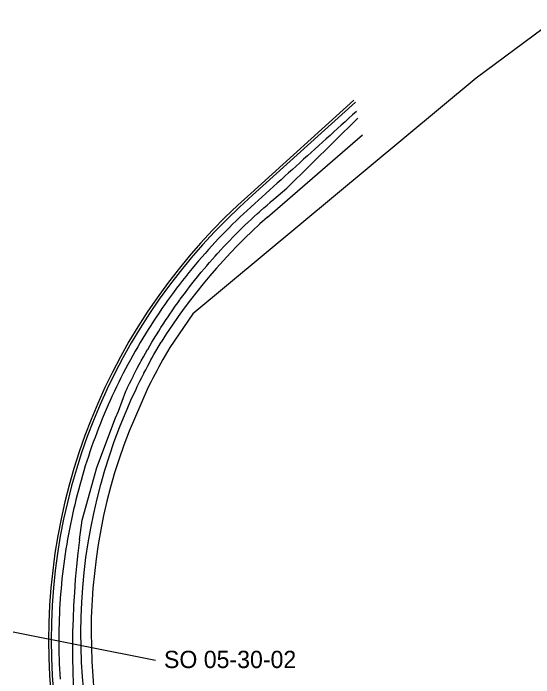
# Model space of a CAD drawing. Extents: x -723225 to -722352, y -1040354 to -1039760.
# Drawn here: x -722611.1 to -722559.9, y -1040117.7 to -1040052.4 of the extents above; entities that cross this region are included whole.
import ezdxf

# ---------------------------------------------------------------- set-up
doc = ezdxf.new("R2010")
doc.units = 0
for name, color, linetype in [('_PS_SO_číslo', 7, 'Continuous'), ('SO 05_30_02', 7, 'Continuous'), ('SO 05_73_06', 7, 'Continuous')]:
    doc.layers.add(name, color=color, linetype=linetype)

msp = doc.modelspace()

# ---------------------------------------------------------------- linework, layer by layer
at = {"layer": '_PS_SO_číslo'}
msp.add_line((-722611.08, -1040113.25), (-722597.09, -1040116.03), dxfattribs=at)
at = {"layer": 'SO 05_30_02'}
for p, q in [((-722577.569, -1040060.933), (-722587.7, -1040070.108)), ((-722577.401, -1040061.118), (-722587.532, -1040070.293)), ((-722586.071, -1040072.432), (-722576.706, -1040064.349))]:
    msp.add_line(p, q, dxfattribs=at)
for points in [[(-722577.314, -1040062.051), (-722577.684, -1040062.387), (-722578.054, -1040062.722), (-722578.054, -1040062.722), (-722578.425, -1040063.058), (-722578.425, -1040063.058), (-722578.795, -1040063.393), (-722579.166, -1040063.729), (-722579.537, -1040064.064), (-722579.907, -1040064.4), (-722580.278, -1040064.736), (-722580.648, -1040065.071), (-722580.649, -1040065.071), (-722581.019, -1040065.407), (-722581.019, -1040065.407), (-722581.39, -1040065.742), (-722581.761, -1040066.078), (-722582.131, -1040066.414), (-722582.502, -1040066.749), (-722582.872, -1040067.084), (-722583.243, -1040067.421), (-722583.613, -1040067.756), (-722583.614, -1040067.756), (-722583.984, -1040068.092), (-722583.984, -1040068.092), (-722584.354, -1040068.427), (-722584.725, -1040068.763), (-722584.725, -1040068.763), (-722585.096, -1040069.099), (-722585.096, -1040069.099), (-722585.467, -1040069.435), (-722585.838, -1040069.77), (-722585.838, -1040069.77), (-722586.209, -1040070.105), (-722586.209, -1040070.106), (-722586.58, -1040070.441), (-722586.951, -1040070.776), (-722586.951, -1040070.776), (-722587.323, -1040071.111), (-722587.323, -1040071.112), (-722587.695, -1040071.446), (-722588.061, -1040071.78), (-722588.422, -1040072.115), (-722588.784, -1040072.455), (-722589.134, -1040072.794), (-722589.495, -1040073.142), (-722589.837, -1040073.487), (-722590.189, -1040073.841), (-722590.528, -1040074.193), (-722590.873, -1040074.552), (-722591.211, -1040074.911), (-722591.544, -1040075.273), (-722591.876, -1040075.639), (-722592.202, -1040076.007), (-722592.532, -1040076.381), (-722592.848, -1040076.751), (-722593.173, -1040077.132), (-722593.486, -1040077.509), (-722593.799, -1040077.891), (-722594.106, -1040078.275), (-722594.414, -1040078.664), (-722594.715, -1040079.054), (-722595.012, -1040079.445), (-722595.31, -1040079.843), (-722595.6, -1040080.24), (-722595.889, -1040080.64), (-722596.176, -1040081.044), (-722596.451, -1040081.445), (-722596.734, -1040081.858), (-722597.012, -1040082.269), (-722597.283, -1040082.679), (-722597.549, -1040083.093), (-722597.812, -1040083.509), (-722598.078, -1040083.932), (-722598.323, -1040084.345), (-722598.578, -1040084.774), (-722598.834, -1040085.205), (-722599.081, -1040085.631), (-722599.316, -1040086.055), (-722599.557, -1040086.492), (-722599.558, -1040086.492), (-722599.8, -1040086.93), (-722600.027, -1040087.359), (-722600.256, -1040087.799), (-722600.479, -1040088.237), (-722600.697, -1040088.678), (-722600.915, -1040089.124), (-722601.127, -1040089.569), (-722601.334, -1040090.015), (-722601.54, -1040090.466), (-722601.74, -1040090.916), (-722601.938, -1040091.369), (-722602.13, -1040091.823), (-722602.319, -1040092.279), (-722602.505, -1040092.737), (-722602.685, -1040093.195), (-722602.862, -1040093.656), (-722603.033, -1040094.117), (-722603.205, -1040094.584), (-722603.366, -1040095.045), (-722603.531, -1040095.517), (-722603.688, -1040095.982), (-722603.842, -1040096.452), (-722603.991, -1040096.922), (-722604.136, -1040097.393), (-722604.277, -1040097.866), (-722604.412, -1040098.338), (-722604.545, -1040098.816), (-722604.677, -1040099.295), (-722604.801, -1040099.77), (-722604.92, -1040100.246), (-722605.038, -1040100.729), (-722605.147, -1040101.206), (-722605.259, -1040101.692), (-722605.363, -1040102.173), (-722605.462, -1040102.655), (-722605.556, -1040103.138), (-722605.649, -1040103.625), (-722605.736, -1040104.111), (-722605.818, -1040104.596), (-722605.895, -1040105.082), (-722605.895, -1040105.082), (-722605.974, -1040105.576), (-722606.044, -1040106.061), (-722606.112, -1040106.551), (-722606.173, -1040107.037), (-722606.233, -1040107.531), (-722606.287, -1040108.021), (-722606.334, -1040108.508), (-722606.383, -1040109.005), (-722606.422, -1040109.491), (-722606.46, -1040109.987), (-722606.49, -1040110.476), (-722606.522, -1040110.975), (-722606.543, -1040111.46), (-722606.564, -1040111.958), (-722606.58, -1040112.452), (-722606.587, -1040112.938), (-722606.595, -1040113.438), (-722606.601, -1040113.937), (-722606.599, -1040114.424), (-722606.591, -1040114.926), (-722606.583, -1040115.414), (-722606.574, -1040115.914), (-722606.551, -1040116.39), (-722606.528, -1040116.89), (-722606.503, -1040117.388), (-722606.476, -1040117.882)], [(-722601.012, -1040092.171), (-722600.737, -1040091.518), (-722600.378, -1040090.55), (-722600.005, -1040089.57), (-722599.884, -1040089.313), (-722599.825, -1040089.19), (-722599.641, -1040088.811), (-722599.454, -1040088.433), (-722599.265, -1040088.057), (-722599.24, -1040088.008), (-722599.072, -1040087.682), (-722598.877, -1040087.309), (-722598.679, -1040086.938), (-722598.562, -1040086.72), (-722598.478, -1040086.567), (-722598.274, -1040086.199), (-722598.068, -1040085.832), (-722597.859, -1040085.466), (-722597.85, -1040085.451), (-722597.647, -1040085.102), (-722597.432, -1040084.74), (-722597.214, -1040084.379), (-722597.105, -1040084.201), (-722596.994, -1040084.02), (-722596.771, -1040083.663), (-722596.578, -1040083.358), (-722596.545, -1040083.307), (-722596.328, -1040082.971), (-722596.317, -1040082.954), (-722596.086, -1040082.601), (-722595.852, -1040082.251), (-722595.616, -1040081.903), (-722595.519, -1040081.761), (-722595.377, -1040081.556), (-722595.135, -1040081.211), (-722594.891, -1040080.868), (-722594.678, -1040080.574), (-722594.644, -1040080.527), (-722594.394, -1040080.187), (-722594.142, -1040079.85), (-722593.888, -1040079.514), (-722593.807, -1040079.409), (-722593.631, -1040079.181), (-722593.371, -1040078.849), (-722593.109, -1040078.52), (-722592.905, -1040078.267), (-722592.844, -1040078.192), (-722592.577, -1040077.866), (-722592.307, -1040077.543), (-722592.035, -1040077.221), (-722591.973, -1040077.149), (-722591.76, -1040076.902), (-722591.484, -1040076.585), (-722591.204, -1040076.27), (-722591.012, -1040076.056), (-722590.985, -1040076.025), (-722590.922, -1040075.956), (-722590.638, -1040075.646), (-722590.352, -1040075.337), (-722590.063, -1040075.03), (-722590.023, -1040074.988), (-722589.772, -1040074.726), (-722589.478, -1040074.424), (-722589.183, -1040074.124), (-722589.007, -1040073.947), (-722588.885, -1040073.826), (-722588.584, -1040073.531), (-722588.282, -1040073.238), (-722587.977, -1040072.947), (-722587.963, -1040072.934), (-722587.67, -1040072.659), (-722587.361, -1040072.373), (-722587.05, -1040072.089), (-722586.893, -1040071.947), (-722586.737, -1040071.808), (-722586.421, -1040071.529), (-722586.103, -1040071.252), (-722585.797, -1040070.99), (-722585.783, -1040070.977), (-722585.435, -1040070.681), (-722584.149, -1040069.586), (-722577.187, -1040062.719), (-722577.187, -1040062.719)], [(-722604.18, -1040118.698), (-722604.268, -1040117.676), (-722604.36, -1040116.208), (-722604.414, -1040114.738), (-722604.43, -1040113.268), (-722604.406, -1040111.797), (-722604.344, -1040110.327), (-722604.284, -1040109.376), (-722604.244, -1040108.86), (-722604.105, -1040107.395), (-722603.928, -1040105.935), (-722603.712, -1040104.48), (-722603.458, -1040103.031), (-722603.166, -1040101.59), (-722602.839, -1040100.166), (-722602.837, -1040100.156), (-722602.47, -1040098.732), (-722602.065, -1040097.318), (-722601.624, -1040095.915), (-722601.146, -1040094.523), (-722600.632, -1040093.145), (-722600.081, -1040091.781), (-722599.887, -1040091.324), (-722599.495, -1040090.432), (-722598.998, -1040089.358), (-722598.874, -1040089.099), (-722598.814, -1040088.975), (-722598.626, -1040088.592), (-722598.436, -1040088.212), (-722598.243, -1040087.832), (-722598.218, -1040087.783), (-722598.047, -1040087.454), (-722597.848, -1040087.078), (-722597.647, -1040086.703), (-722597.527, -1040086.484), (-722597.442, -1040086.329), (-722597.235, -1040085.958), (-722596.541, -1040084.735)], [(-722604.567, -1040104.198), (-722604.295, -1040102.259), (-722603.517, -1040099.442), (-722602.86, -1040097.061), (-722601.012, -1040092.171)]]:
    msp.add_lwpolyline(points, dxfattribs=at)
for radius in [58.46, 58.21]:
    msp.add_arc((-722549.145, -1040114.051), radius, 131.25938, 185.13439, dxfattribs=at)
for centre, major_axis, ratio, start_param, end_param in [((-722548.371, -1040115.029), (-39.084, -42.585), 0.983948, 4.610283, 4.890699), ((-722517.018, -1040111.528), (79.312, 40.575), 0.952893, 2.563333, 2.804578)]:
    msp.add_ellipse(centre, major_axis=major_axis, ratio=ratio, start_param=start_param, end_param=end_param, dxfattribs=at)
at = {"layer": 'SO 05_73_06'}
msp.add_lwpolyline([(-722551.456, -1040048.318), (-722565.54, -1040058.784), (-722593.424, -1040081.963), (-722595.687, -1040085.256), (-722596.363, -1040086.448), (-722596.767, -1040087.179), (-722596.966, -1040087.548), (-722597.161, -1040087.918), (-722597.353, -1040088.287), (-722597.543, -1040088.662), (-722597.73, -1040089.036), (-722597.914, -1040089.412), (-722599.681, -1040093.492), (-722600.205, -1040094.861), (-722600.674, -1040096.227), (-722601.108, -1040097.605), (-722601.505, -1040098.994), (-722601.866, -1040100.398), (-722602.189, -1040101.801), (-722602.475, -1040103.217), (-722602.725, -1040104.64), (-722602.937, -1040106.069), (-722603.248, -1040108.945), (-722603.407, -1040111.826), (-722603.43, -1040113.27), (-722603.361, -1040116.158), (-722603.142, -1040119.041)], dxfattribs=at)

# ---------------------------------------------------------------- texts
at = {"layer": '_PS_SO_číslo'}
msp.add_text('SO 05-30-02', height=1.7, dxfattribs=at).set_placement((-722596.25, -1040116.8))

doc.saveas('drawing.dxf')
